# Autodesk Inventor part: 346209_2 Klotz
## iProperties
Created: 2006-10
Part Number: 346209_2 Klotz
Material: St 37-2 K
Description: Platte
Document SubType Name: Modeling
Designer: OSchmidt
Density: 7.85 g/cm^3
Mass: 18.7378 g
Surface Area: 16.6078 cm^2
Volume: 2.38699 cm^3
Author: Natti_01
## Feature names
1. Extrusion4
2. Bohrung1 [Hole]
